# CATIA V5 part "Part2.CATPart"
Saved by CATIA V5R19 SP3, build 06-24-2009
Part number: Part1
Bounding box of the stored display mesh (mm): x -40 to 70, y -30 to 40, z 0 to 23
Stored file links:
  C:\TEMP\Part2.CATPart
  C:\Programme\Dassault Systemes\B19\intel_a\reffiles\standard\MetricThickPitch.txt
  C:\TEMP\Produkt1.CATProduct
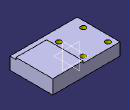
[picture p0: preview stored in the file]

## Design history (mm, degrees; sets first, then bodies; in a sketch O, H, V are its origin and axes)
Set1
  DatumSurface1: linked copy from another document
Body1 (main body)
  Sketch1 on xy-plane, origin (0, 0, 0), H (1, 0, 0), V (0, 1, 0)
    line L1 (-40, -30) -> (70, -30)
    line L2 (70, -30) -> (70, 40)
    line L3 (70, 40) -> (-40, 40)
    line L4 (-40, 40) -> (-40, -30)
    horizontal: L1 H, L3 H
    vertical: L2 V, L4 V
  Pad1: profile Sketch1, direction (0, 0, 1), length 20
  Sketch2 on end face of Pad1, origin (0, 0, 20), H (1, 0, 0), V (0, 1, 0)
    line L1 (70, 40) -> (20, 40)
    line L2 (20, 40) -> (20, -20)
    line L3 (20, -20) -> (70, -20)
    line L4 (70, -20) -> (70, 40)
    horizontal: L1 H, L3 H
    vertical: L2 V, L4 V
  Pad2: profile Sketch2, direction (0, 0, 1), length 3
  Sketch3 on end face of Pad1, origin (0, 0, 20), H (1, 0, 0), V (0, 1, 0)
    projected line E1 (20, -20) -> (-40, -20) from edge of DatumSurface1
    projected line E2 (20, 40) -> (20, -20) from edge of DatumSurface1
    projected line E3 (-40, 40) -> (20, 40) from edge of DatumSurface1
    projected line E4 (-40, -20) -> (-40, 40) from edge of DatumSurface1
    projected circle E5 centre (-17.5533, 11.7737) radius 2.4585 from edge of DatumSurface1
    projected circle E6 centre (-9.4711, 11.2027) radius 2.4585 from edge of DatumSurface1
    projected circle E7 centre (-30, -10) radius 7.5 from edge of DatumSurface1
    projected circle E8 centre (10, -10) radius 7.5 from edge of DatumSurface1
    projected circle E9 centre (-30, 30) radius 7.5 from edge of DatumSurface1
    projected circle E10 centre (10, 30) radius 7.5 from edge of DatumSurface1
    projected circle E11 centre (-15.5899, 5.8915) radius 2.4585 from edge of DatumSurface1
    projected circle E12 centre (-10.0422, 3.1205) radius 2.4585 from edge of DatumSurface1
    projected circle E13 centre (-4.16, 5.0839) radius 2.4585 from edge of DatumSurface1
    point P9 (10, -10)
    point P10 (-30, -10)
    point P11 (-30, 30)
    point P12 (10, 30)
    concentricity: P9 E8, P10 E7, P11 E9, P12 E10
  Sketch4 on end face of Pad1, origin (10, -10, 20), H (1, 0, 0), V (0, 1, 0)
    point P1 (0, 0)
    reference projected point E1 (0, 0) from Sketch3.P9
    coincidence: E1 P1
  Hole1: placed by Sketch4, at (10, -10, 20) direction (0, 0, -1), diameter 8.376, through (limit type 3), threaded "M10", thread diameter 10, thread depth 10, pitch 1.5
  UserPattern1: of Hole1, copies 4, at the points of Sketch3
